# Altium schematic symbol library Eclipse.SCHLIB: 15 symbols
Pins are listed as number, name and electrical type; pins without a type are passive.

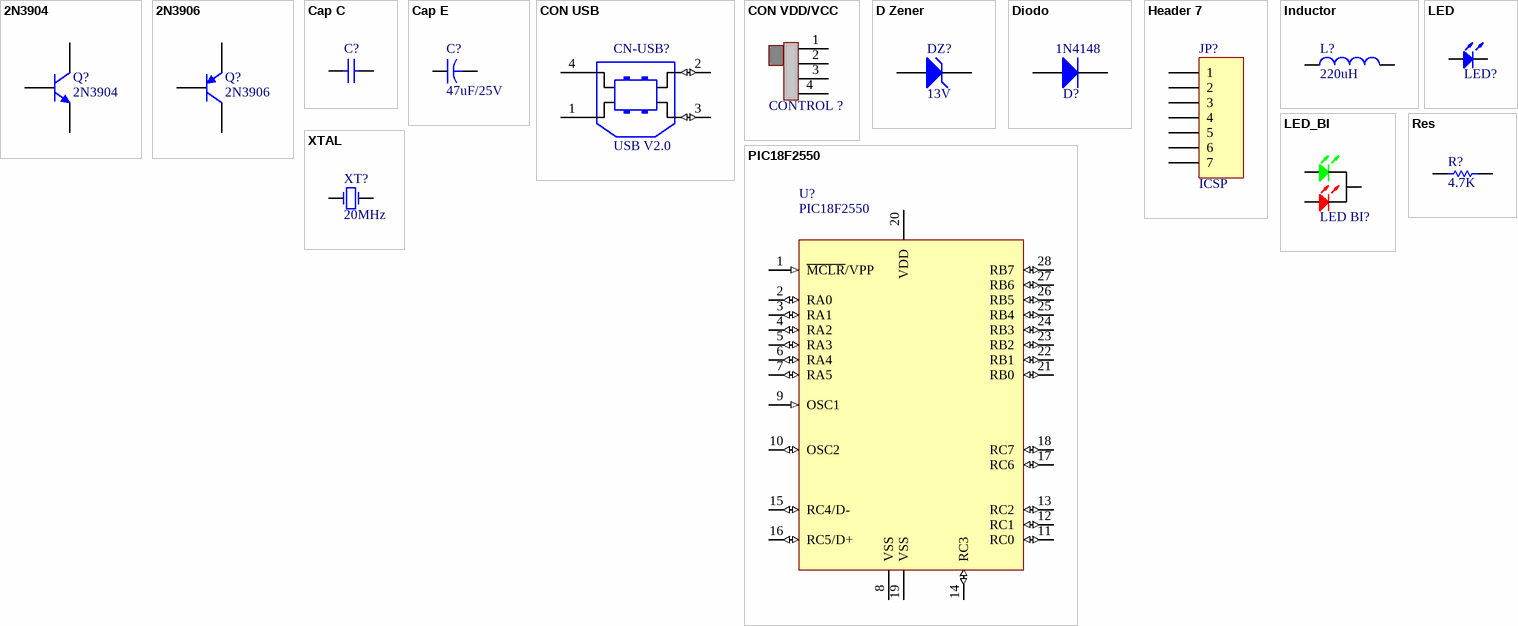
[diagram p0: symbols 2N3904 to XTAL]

## 2N3904
designator Q?
NPN Uso general; Manufacturer: Generic Components; Revision 1: 11-July-2000: SIM Model Added.; Revision 2: July-2002: Re-released for DXP Platform.; Class I: Discrete; Class II: BJT - Low Power
footprint Q123 0.1
pins: 1 E, 2 B, 3 C

## 2N3906
designator Q?
PNP Uso General; Manufacturer: Generic Components; Revision 1: 11-July-2000: SIM Model Added.; Revision 2: July-2002: Re-released for DXP Platform.; Class I: Discrete; Class II: BJT - Low Power
footprint Q123 0.1
pins: 1 E, 2 B, 3 C

## Cap C
designator C?, comment CC  (value not drawn)
Capacitor Ceramico; Manufacturer: Generic Components; Class I: Passive; Value: 15pF
footprint CC 0.15
pins: 1, 2

## Cap E
designator C?, comment value 47uF/25V  (hidden comment: Cap)
Capacitor Electrolitico; Manufacturer: Generic Components; Class I: Passive
footprint CE-1.7
pins: 1, 2

## CON USB
designator CN-USB?, comment USB V2.0
CON USB
footprint USB2.5-2H4D (Connector; USB1.1, Type B, Thru-Hole; 4 Position; Right Angle)
pins: 1 (power), 2 (io), 3 (io), 4 (power)

## CON VDD/VCC
designator CONTROL ?, comment INPUT  (value not drawn)
CON VDD/VCC; Manufacturer: Generic Components; Class I: Connector
footprint HDR1X4
pins: 1, 2, 3, 4

## D Zener
designator DZ?, comment 13V
Diodo Zener; Manufacturer: Generic Components; Class I: Discrete; Class II: Diode - Zener
footprint DIODOZ 6.5MM
footprint DIODOZ
pins: 1 A, 2 K

## Diodo
designator D?  Class II: 1N4148  (hidden comment: Diodo)
Diodo de uso general; Manufacturer: Generic Components; Class I: Discrete
footprint DIODO 10MM
footprint DIODO 4MIL
pins: 1 A, 2 K

## Header 7
designator JP?, comment ICSP
Header, 7-Pin
footprint HDR1X7H
pins: 1, 2, 3, 4, 5, 6, 7

## Inductor
designator L?  value 220uH  (hidden comment: Inductor)
footprint L 1.2MM
footprint L
pins: 1, 2

## LED
designator LED?  (value not drawn)
Manufacturer: Generic Components; Class I: Optoelectronic
footprint LED-0
pins: 1 A, 2 K

## LED_BI
designator LED BI?, comment LED  (value not drawn)
LED_BI; Manufacturer: Generic Components; Class I: Optoelectronic
footprint LED-BI
pins: 1 A, 2 A, 3 K

## PIC18F2550
designator U?
High Performance, Microcontroller with 10-Bit A/D, 16K EPROM, 28-Pin SOIC, Standard Volt Range, Extended Temperature; PackageDocument: DS00049W_2003; Note: Pin compatible with 28-pin PIC16C7X devices.; Note: Not recommended for new designs. Consider PIC18F242 instead.; Note: RB3 is the alternate pin for the CCP2 pin multiplexing.
footprint DIP-28
pins: 1 ~{MCLR}/VPP (in), 2 RA0 (io), 3 RA1 (io), 4 RA2 (io), 5 RA3 (io), 6 RA4 (io), 7 RA5 (io), 8 VSS (power), 9 OSC1 (in), 10 OSC2 (io), 11 RC0 (io), 12 RC1 (io), 13 RC2 (io), 14 RC3 (io), 15 RC4/D- (io), 16 RC5/D+ (io), 17 RC6 (io), 18 RC7 (io), 19 VSS (power), 20 VDD (power), 21 RB0 (io), 22 RB1 (io), 23 RB2 (io), 24 RB3 (io), 25 RB4 (io), 26 RB5 (io), 27 RB6 (io), 28 RB7 (io)

## Res
designator R?  value 4.7K  (hidden comment: Res)
Resistor; Manufacturer: Generic Components; Class I: Passive
footprint AXIAL 4MIL
footprint AXIAL 10MM
pins: 1, 2

## XTAL
designator XT?, comment 20MHz
Crystal Oscillator; Manufacturer: Generic Components
footprint XT 0.17
pins: 1 OSC1, 2 OSC2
